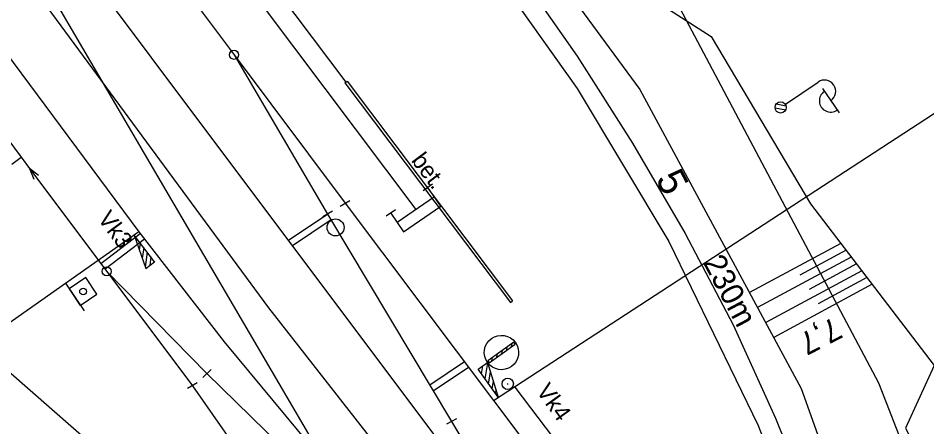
# Model space of a CAD drawing. Extents: x -804166 to -803706, y -1151030 to -1150147.
# Drawn here: x -803991 to -803910.7, y -1150395.9 to -1150359.8 of the extents above; entities that cross this region are included whole.
import ezdxf

# ---------------------------------------------------------------- set-up
doc = ezdxf.new("R2010")
doc.units = 0
for name, color, linetype in [('0381KM032-037P - Vrstva 1', 7, 'Continuous'), ('0381KM032-037P - Vrstva 15', 7, 'Continuous'), ('0381KM032-037P - Vrstva 16', 7, 'Continuous'), ('0381KM032-037P - Vrstva 2', 7, 'Continuous'), ('0381KM032-037P - Vrstva 25', 7, 'Continuous'), ('0381KM032-037P - Vrstva 27', 7, 'Continuous'), ('0381KM032-037P - Vrstva 3', 7, 'Continuous'), ('0381KM032-037P - Vrstva 4', 7, 'Continuous'), ('0381KM032-037P - Vrstva 48', 7, 'Continuous'), ('0381KM032-037P - Vrstva 49', 7, 'Continuous'), ('0381KM032-037P - Vrstva 51', 7, 'Continuous'), ('0381KM032-037P - Vrstva 7', 7, 'Continuous'), ('hran DP - hran DP', 7, 'Continuous'), ('vyt_sit - polygon', 7, 'Continuous')]:
    doc.layers.add(name, color=color, linetype=linetype)

msp = doc.modelspace()

# ---------------------------------------------------------------- linework, layer by layer
at = {"layer": '0381KM032-037P - Vrstva 1'}
for points in [[(-804087.926, -1150205.285), (-804078.707, -1150215.283), (-804072.371, -1150222.524), (-804072.077, -1150222.855), (-804071.467, -1150223.584), (-804065.479, -1150230.817), (-804059.467, -1150238.509), (-804055.553, -1150243.678), (-804054.356, -1150245.269), (-804043.889, -1150259.222), (-804035.374, -1150270.613), (-804034.4, -1150271.93), (-804017.97, -1150293.92), (-804002.6, -1150314.46), (-803985.38, -1150337.43), (-803955.87, -1150376.72)], [(-804090.387, -1150214.375), (-804086.648, -1150219.546), (-804073.823, -1150237.114), (-804072.555, -1150238.826), (-804064.047, -1150250.31), (-804062.807, -1150251.974), (-804052.288, -1150266.049), (-804042.5, -1150279.11), (-804026.546, -1150300.334), (-804011.272, -1150320.629), (-803993.373, -1150344.487), (-803965.171, -1150382.072), (-803953.841, -1150397.189)], [(-804093.97, -1150217.423), (-804088.165, -1150225.674), (-804077.507, -1150240.279), (-804068.519, -1150252.214), (-804067.312, -1150253.815), (-804055.014, -1150270.122), (-804046.09, -1150281.931), (-804030.046, -1150303.209), (-804014.756, -1150323.518), (-803996.92, -1150347.354), (-803968.884, -1150385.416), (-803942.597, -1150419.033)], [(-804095.554, -1150218.377), (-804090.738, -1150227.081), (-804084.011, -1150238.21), (-804078.761, -1150245.777), (-804072.115, -1150254.848), (-804070.853, -1150256.555), (-804059.975, -1150271.287), (-804049.56, -1150285.37), (-804034.127, -1150306.216), (-804018.794, -1150326.862), (-804001.176, -1150350.631), (-803980.37, -1150378.683), (-803972.82, -1150388.417), (-803965.206, -1150397.597)], [(-804088.45, -1150239.448), (-804070.362, -1150264.071), (-804054.977, -1150285.047), (-804052.95, -1150287.79), (-804037.556, -1150308.636), (-804021.871, -1150329.906), (-804004.483, -1150353.558), (-803990.764, -1150372.094)], [(-804011.14, -1150262.39), (-804005.45, -1150273.41), (-803998.73, -1150284.85), (-803991.51, -1150295.63), (-803978.8, -1150312.77), (-803963.69, -1150332.99), (-803952.21, -1150348.36), (-803946.3, -1150356.39), (-803941.6, -1150363.14), (-803936.71, -1150370.83), (-803932.05, -1150378.84), (-803927.78, -1150386.91), (-803924.06, -1150395.18), (-803920.62, -1150403.65), (-803918.06, -1150410.86), (-803915.07, -1150420.32), (-803912.96, -1150427.25), (-803910.49, -1150435.34), (-803907.334, -1150445.05), (-803903.668, -1150454.381), (-803897.938, -1150464.596), (-803891.973, -1150476.598)], [(-803981.901, -1150349.725), (-803980.965, -1150350.974), (-803971.944, -1150363.027), (-803962.118, -1150376.153)], [(-803981.901, -1150349.725), (-803980.965, -1150350.974), (-803971.944, -1150363.027), (-803963.662, -1150377.119)], [(-803990.764, -1150372.094), (-803990.029, -1150373.085), (-803975.617, -1150392.296)], [(-803990.764, -1150372.094), (-803990.029, -1150373.085), (-803983.202, -1150382.185), (-803974.334, -1150391.21)], [(-803962.118, -1150376.153), (-803948.983, -1150393.601), (-803935.254, -1150411.887)], [(-803963.662, -1150377.119), (-803952.72, -1150395.461)], [(-803974.334, -1150391.21), (-803966.535, -1150398.856)], [(-803975.617, -1150392.296), (-803939.473, -1150444.116), (-803928.265, -1150459.416), (-803914.534, -1150477.731)], [(-803952.72, -1150395.461), (-803943.112, -1150411.456), (-803938.373, -1150417.729), (-803937.129, -1150419.412)]]:
    msp.add_lwpolyline(points, dxfattribs=at)
at = {"layer": '0381KM032-037P - Vrstva 15'}
for p, q in [((-803954.374, -1150374.481), (-803955.199, -1150375.047)), ((-803954.221, -1150375.589), (-803957.519, -1150377.851)), ((-803957.673, -1150376.744), (-803958.497, -1150377.309))]:
    msp.add_line(p, q, dxfattribs=at)
msp.add_lwpolyline([(-803958.085, -1150377.027), (-803956.954, -1150378.676), (-803953.655, -1150376.413), (-803954.786, -1150374.764)], dxfattribs=at)
at = {"layer": '0381KM032-037P - Vrstva 16'}
for p, q in [((-803962.142, -1150365.503), (-803961.942, -1150365.353)), ((-803962.142, -1150365.503), (-803947.503, -1150384.94)), ((-803961.942, -1150365.353), (-803947.303, -1150384.79)), ((-803947.503, -1150384.94), (-803947.303, -1150384.79))]:
    msp.add_line(p, q, dxfattribs=at)
at = {"layer": '0381KM032-037P - Vrstva 2'}
for p, q in [((-803991.586, -1150372.712), (-803990.764, -1150372.094)), ((-803962.55, -1150376.405), (-803961.686, -1150375.901)), ((-803963.228, -1150376.871), (-803964.096, -1150377.367)), ((-803983.202, -1150382.185), (-803974.334, -1150391.21)), ((-803973.978, -1150390.859), (-803974.69, -1150391.561)), ((-803975.191, -1150392.034), (-803976.043, -1150392.558)), ((-803952.278, -1150395.227), (-803953.162, -1150395.695)), ((-803952.72, -1150395.461), (-803943.112, -1150411.456))]:
    msp.add_line(p, q, dxfattribs=at)
for points in [[(-803981.901, -1150349.725), (-803980.965, -1150350.974), (-803971.944, -1150363.027), (-803962.118, -1150376.153)], [(-803971.944, -1150363.027), (-803963.662, -1150377.119)], [(-803990.764, -1150372.094), (-803990.029, -1150373.085), (-803983.202, -1150382.185), (-803975.617, -1150392.296)], [(-803989.246, -1150373.707), (-803990.029, -1150373.085), (-803989.662, -1150374.015)]]:
    msp.add_lwpolyline(points, dxfattribs=at)
for centre in [(-803971.944, -1150363.027), (-803983.202, -1150382.185)]:
    msp.add_circle(centre, 0.4, dxfattribs=at)
at = {"layer": '0381KM032-037P - Vrstva 25'}
for p, q in [((-803923.18, -1150367.4), (-803920.285, -1150365.433)), ((-803919.892, -1150366.012), (-803918.431, -1150368.163)), ((-803923.983, -1150367.368), (-803923.119, -1150367.533)), ((-803924.09, -1150367.729), (-803923.149, -1150367.908))]:
    msp.add_line(p, q, dxfattribs=at)
msp.add_circle((-803923.594, -1150367.681), 0.5, dxfattribs=at)
for centre, start, end in [((-803919.723, -1150366.26), 304.19448, 124.19448), ((-803919.172, -1150367.094), 123.49191, 304.89706)]:
    msp.add_arc(centre, 1, start, end, dxfattribs=at)
at = {"layer": '0381KM032-037P - Vrstva 27'}
msp.add_line((-803947.781, -1150392.134), (-803947.681, -1150392.134), dxfattribs=at)
msp.add_circle((-803947.731, -1150392.134), 0.5, dxfattribs=at)
at = {"layer": '0381KM032-037P - Vrstva 3'}
for p, q in [((-803948.983, -1150393.601), (-803893.865, -1150357.656)), ((-803980.37, -1150378.683), (-804019.008, -1150405.813)), ((-803980.57, -1150379.244), (-803980.596, -1150379.485)), ((-803980.25, -1150379.661), (-803980.331, -1150380.274)), ((-803979.931, -1150380.078), (-803980.065, -1150381.04)), ((-803979.611, -1150380.494), (-803979.793, -1150381.825)), ((-803979.292, -1150380.911), (-803979.402, -1150381.657)), ((-803978.978, -1150381.32), (-803978.986, -1150381.338)), ((-803985.056, -1150382.728), (-803986.528, -1150383.718)), ((-803984.066, -1150384.2), (-803985.056, -1150382.728)), ((-803986.858, -1150383.228), (-803985.208, -1150385.68)), ((-803986.528, -1150383.718), (-803985.538, -1150385.19)), ((-803985.538, -1150385.19), (-803984.066, -1150384.2)), ((-803948.258, -1150389.466), (-803948.211, -1150389.176)), ((-803947.82, -1150389.151), (-803947.781, -1150388.867)), ((-803947.388, -1150388.841), (-803947.342, -1150388.551)), ((-803947.103, -1150388.636), (-803947.097, -1150388.598)), ((-803949.135, -1150390.097), (-803949.081, -1150389.802)), ((-803948.697, -1150389.782), (-803948.649, -1150389.491)), ((-803950.053, -1150391.256), (-803949.939, -1150390.552)), ((-803949.738, -1150391.694), (-803949.507, -1150390.287)), ((-803949.428, -1150392.125), (-803949.254, -1150391.102)), ((-803949.119, -1150392.556), (-803949, -1150391.917)), ((-803948.804, -1150392.994), (-803948.752, -1150392.724))]:
    msp.add_line(p, q, dxfattribs=at)
for points in [[(-803980.767, -1150378.987), (-803979.757, -1150381.929), (-803978.972, -1150381.327), (-803980.767, -1150378.987)], [(-803947.081, -1150388.62), (-803947.203, -1150388.451), (-803949.504, -1150390.106), (-803949.383, -1150390.275), (-803947.081, -1150388.62)], [(-803948.577, -1150393.309), (-803950.348, -1150390.846), (-803949.522, -1150390.252), (-803948.577, -1150393.309)]]:
    msp.add_lwpolyline(points, dxfattribs=at)
msp.add_lwpolyline([(-803947.081, -1150388.62), (-803947.203, -1150388.451), (-803949.504, -1150390.106), (-803949.383, -1150390.275)], close=True, dxfattribs=at)
msp.add_circle((-803985.295, -1150383.96), 0.296, dxfattribs=at)
msp.add_ellipse((-803948.291, -1150389.364), major_axis=(-1.233, -0.887), ratio=0.999996, dxfattribs=at)
at = {"layer": '0381KM032-037P - Vrstva 4'}
for points in [[(-804015.087, -1150257.699), (-804005.607, -1150276.645), (-803997.811, -1150289.613), (-803985.988, -1150305.967), (-803963.827, -1150335.545), (-803947.69, -1150357.387), (-803941.599, -1150366.016), (-803933.495, -1150379.543), (-803925.569, -1150395.827), (-803919.567, -1150411.363), (-803915.11, -1150425.701)], [(-804033.342, -1150270.468), (-804023.506, -1150283.74), (-804006.754, -1150306.055), (-804002.754, -1150311.23), (-803984.52, -1150335.594), (-803962.042, -1150365.446)]]:
    msp.add_lwpolyline(points, dxfattribs=at)
at = {"layer": '0381KM032-037P - Vrstva 48'}
for p, q in [((-803918.269, -1150379.708), (-803926.342, -1150384.066)), ((-803917.808, -1150380.311), (-803921.897, -1150382.519)), ((-803917.347, -1150380.915), (-803925.629, -1150385.386)), ((-803916.886, -1150381.518), (-803921.08, -1150383.782)), ((-803916.425, -1150382.122), (-803924.917, -1150386.706)), ((-803915.964, -1150382.725), (-803920.262, -1150385.046)), ((-803915.503, -1150383.329), (-803924.204, -1150388.026))]:
    msp.add_line(p, q, dxfattribs=at)
at = {"layer": '0381KM032-037P - Vrstva 49'}
msp.add_line((-803929.733, -1150361.392), (-803920.94, -1150376.21), dxfattribs=at)
for points in [[(-804010.873, -1150255.863), (-804001.608, -1150274.672), (-803994.699, -1150286.679), (-803981.461, -1150304.357), (-803936.046, -1150366.093), (-803921.768, -1150392.538), (-803912.222, -1150419.282), (-803908.812, -1150430.908)], [(-803989.471, -1150289.341), (-803982.88, -1150300.61), (-803979.03, -1150305.25), (-803971.78, -1150314.79), (-803959.62, -1150330.2), (-803952.37, -1150339.47), (-803944.88, -1150350.15), (-803937.924, -1150356.122), (-803929.733, -1150361.392)], [(-803920.94, -1150376.21), (-803910.018, -1150390.511), (-803912.553, -1150396.059), (-803903.866, -1150412.95), (-803903.684, -1150418.644), (-803901.421, -1150428.97), (-803900.537, -1150437.639), (-803895.89, -1150448.56), (-803892.01, -1150457.3), (-803887.412, -1150463.602), (-803875.883, -1150484.91), (-803874.859, -1150484.495), (-803872.322, -1150492.497), (-803872.997, -1150496.546), (-803874.041, -1150498.946)], [(-803995.514, -1150387.867), (-803978.951, -1150402.371), (-803967.974, -1150412.011), (-803952.572, -1150434.32)]]:
    msp.add_lwpolyline(points, dxfattribs=at)
at = {"layer": '0381KM032-037P - Vrstva 51'}
msp.add_line((-803947.116, -1150392.441), (-803936.561, -1150406.256), dxfattribs=at)
msp.add_lwpolyline([(-804015.087, -1150257.699), (-804005.607, -1150276.645), (-803997.811, -1150289.613), (-803985.988, -1150305.967), (-803963.827, -1150335.545), (-803947.69, -1150357.387), (-803941.599, -1150366.016), (-803933.495, -1150379.543), (-803925.569, -1150395.827), (-803919.567, -1150411.363), (-803915.11, -1150425.701)], dxfattribs=at)
at = {"layer": '0381KM032-037P - Vrstva 7'}
for p, q in [((-803963.66, -1150377.122), (-803967.136, -1150379.453)), ((-803963.353, -1150377.638), (-803966.776, -1150379.934)), ((-803980.236, -1150378.856), (-803983.711, -1150381.507)), ((-803979.868, -1150379.33), (-803983.351, -1150381.987)), ((-803951.556, -1150390.195), (-803954.63, -1150392.26)), ((-803951.195, -1150390.676), (-803954.322, -1150392.776))]:
    msp.add_line(p, q, dxfattribs=at)
msp.add_circle((-803962.962, -1150378.293), 0.75, dxfattribs=at)
at = {"layer": 'hran DP - hran DP'}
for p, q in [((-803936.41, -1150351.52), (-803914.94, -1150392.05)), ((-803914.94, -1150392.05), (-803912.08, -1150399.4))]:
    msp.add_line(p, q, dxfattribs=at)
at = {"layer": 'vyt_sit - polygon'}
msp.add_line((-803955.931, -1150412.633), (-804016.513, -1150309.123), dxfattribs=at)

# ---------------------------------------------------------------- texts
at = {"layer": '0381KM032-037P - Vrstva 1'}
for s, height, p in [('5', 2.5, (-803934.699, -1150374.008)), ('230m', 2, (-803930.503, -1150381.37))]:
    msp.add_text(s, height=height, rotation=297.88422, dxfattribs=at).set_placement(p)
at = {"layer": '0381KM032-037P - Vrstva 16'}
msp.add_text('bet.', height=1.5, rotation=306.98528, dxfattribs=at).set_placement((-803956.326, -1150372.385))
at = {"layer": '0381KM032-037P - Vrstva 3'}
for s, rotation, p in [('Vk3', 306.52798, (-803984.06, -1150377.526)), ('Vk4', 305.71645, (-803945.266, -1150392.776))]:
    msp.add_text(s, height=1.5, rotation=rotation, dxfattribs=at).set_placement(p)
at = {"layer": '0381KM032-037P - Vrstva 48'}
msp.add_text('7,7', height=2, rotation=207.3698, dxfattribs=at).set_placement((-803918.884, -1150386.177))

doc.saveas('drawing.dxf')
